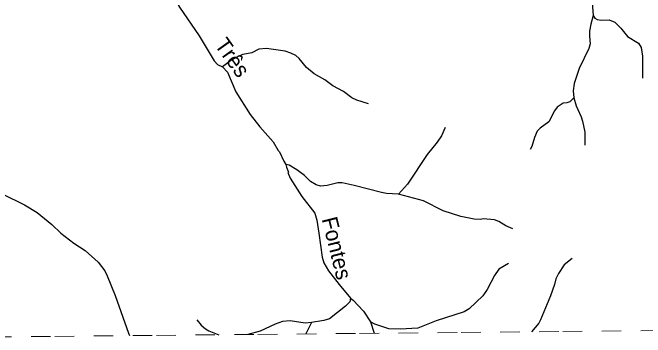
# Model space of a CAD drawing. Extents: x 346.5 to 372.4, y 7400.3 to 7428.2.
# Drawn here: x 358.605 to 361.849, y 7400.435 to 7402.098 of the extents above; entities that cross this region are included whole.
import ezdxf
from ezdxf.enums import TextEntityAlignment as Align

# ---------------------------------------------------------------- set-up
doc = ezdxf.new("R2010")
doc.units = 0
doc.header["$LTSCALE"] = 0.032
doc.linetypes.add('SHORT_DASHED', pattern=[2.7, 1.5, -1.2])
doc.layers.add('53', color=7, linetype='SHORT_DASHED', lineweight=13)
doc.layers.add('7', color=7, linetype='Continuous', lineweight=25)
doc.layers.add('61', color=7, linetype='Continuous')

msp = doc.modelspace()

# ---------------------------------------------------------------- linework, layer by layer
at = {"layer": '53'}
msp.add_lwpolyline([(358.2999, 7400.4352), (358.8209, 7400.4403), (359.3419, 7400.4453), (359.863, 7400.4502), (360.384, 7400.4552), (360.905, 7400.4602), (361.426, 7400.4651), (361.947, 7400.47), (362.4681, 7400.4749), (362.9891, 7400.4798), (363.5101, 7400.4846), (364.0311, 7400.4895), (364.5521, 7400.4943)], dxfattribs=at)
at = {"layer": '7'}
for p, q in [((360.1374, 7400.5116), (360.1088, 7400.4525)), ((360.4409, 7400.5141), (360.4592, 7400.4559))]:
    msp.add_line(p, q, dxfattribs=at)
for points in [[(361.3885, 7403.2094), (361.4008, 7403.1696), (361.4271, 7403.1274), (361.4319, 7403.1242), (361.4534, 7403.0293), (361.463, 7403.0038), (361.4981, 7402.9488), (361.6072, 7402.8189), (361.6288, 7402.7807), (361.6391, 7402.744), (361.6439, 7402.693), (361.6407, 7402.642), (361.6152, 7402.5496), (361.6136, 7402.5241), (361.6152, 7402.4603), (361.6327, 7402.3583), (361.6327, 7402.3041), (361.6232, 7402.2587), (361.5913, 7402.2165), (361.5754, 7402.175), (361.5819, 7402.0837)], [(359.2743, 7402.5266), (359.3296, 7402.4269), (359.3941, 7402.2547), (359.4132, 7402.2117), (359.4372, 7402.1686), (359.4611, 7402.1256), (359.5623, 7401.979), (359.6388, 7401.8507), (359.6555, 7401.833), (359.6805, 7401.821)], [(361.5819, 7402.0837), (361.5706, 7402.0387), (361.5634, 7402.0029), (361.5626, 7401.9774), (361.5658, 7401.9391), (361.5594, 7401.9136), (361.51, 7401.8116), (361.4845, 7401.7351), (361.4797, 7401.6969), (361.4822, 7401.6611)], [(361.5819, 7402.0837), (361.5904, 7402.0702), (361.6025, 7402.0626), (361.6248, 7402.0602), (361.6638, 7402.0618), (361.6933, 7402.0499), (361.7244, 7402.0188), (361.7571, 7401.9758), (361.8144, 7401.9415), (361.8272, 7401.92), (361.8352, 7401.8754), (361.8352, 7401.763)], [(360.4302, 7401.6315), (360.3704, 7401.649), (360.3441, 7401.6626), (360.3011, 7401.6945), (360.2477, 7401.7231), (360.2054, 7401.7534), (360.1504, 7401.7853), (360.1122, 7401.8172), (360.0739, 7401.8626), (360.0564, 7401.8785), (360.0309, 7401.8913), (360.0022, 7401.9001), (359.9066, 7401.9136), (359.8667, 7401.9104), (359.8309, 7401.8921), (359.7854, 7401.8833), (359.7679, 7401.8761), (359.7287, 7401.8561), (359.6805, 7401.821)], [(359.6805, 7401.821), (359.7073, 7401.7933), (359.7496, 7401.6921), (359.8229, 7401.5757), (359.8723, 7401.5128), (359.9416, 7401.437), (359.9671, 7401.3916), (359.9735, 7401.3852), (359.9949, 7401.3372), (360.0065, 7401.32)], [(361.4822, 7401.6611), (361.4622, 7401.6418), (361.4471, 7401.6355), (361.4279, 7401.6339), (361.3969, 7401.614), (361.3833, 7401.5948), (361.3538, 7401.5391), (361.3092, 7401.5056), (361.2941, 7401.4904), (361.2805, 7401.4578), (361.2677, 7401.4131), (361.2582, 7401.3964)], [(361.4822, 7401.6611), (361.4941, 7401.6203), (361.5204, 7401.5646), (361.5275, 7401.5422), (361.5387, 7401.4865), (361.5387, 7401.4187)], [(360.8223, 7401.5096), (360.8039, 7401.4673), (360.7824, 7401.4355), (360.7306, 7401.3717), (360.6294, 7401.2203), (360.5843, 7401.1691)], [(360.0065, 7401.32), (360.0086, 7401.3062), (360.0193, 7401.2812), (360.0165, 7401.2785), (360.0277, 7401.2506), (360.0883, 7401.1565), (360.1552, 7401.0704), (360.1656, 7401.0354), (360.1743, 7400.9684), (360.1919, 7400.8457), (360.2006, 7400.817), (360.2253, 7400.7756), (360.2795, 7400.7054), (360.338, 7400.6363)], [(360.5843, 7401.1691), (360.5218, 7401.1716), (360.4963, 7401.1764), (360.3561, 7401.2131), (360.2955, 7401.2258), (360.2732, 7401.2258), (360.2174, 7401.2123), (360.1839, 7401.2099), (360.1616, 7401.2163), (360.1329, 7401.2338), (360.1018, 7401.2641), (360.0628, 7401.2936), (360.0222, 7401.3169), (360.0065, 7401.32)], [(358.5518, 7401.1708), (358.6665, 7401.1135), (358.7303, 7401.0752), (358.8068, 7401.0131), (358.8514, 7400.9692), (358.9184, 7400.9166), (358.9773, 7400.88), (359.0435, 7400.8194), (359.0777, 7400.7756), (359.0905, 7400.7501), (359.1303, 7400.6497), (359.1997, 7400.4568), (359.2037, 7400.444)], [(361.1697, 7400.99), (361.1339, 7401.0067), (361.0988, 7401.0282), (361.0765, 7401.0362), (361.0175, 7401.0417), (361.0048, 7401.0386), (360.9713, 7401.0402), (360.9028, 7401.0537), (360.8135, 7401.0832), (360.7115, 7401.1342), (360.5843, 7401.1691)], [(361.4742, 7400.8385), (361.4335, 7400.8059), (361.4048, 7400.7628), (361.3897, 7400.7341), (361.3841, 7400.7054), (361.3634, 7400.6481), (361.3116, 7400.5245), (361.3028, 7400.507), (361.2664, 7400.4636)], [(361.1474, 7400.8138), (361.0988, 7400.7843), (361.0757, 7400.7517), (361.0382, 7400.6799), (361.0159, 7400.648), (360.9458, 7400.5811), (360.9203, 7400.5652), (360.7768, 7400.5197), (360.6828, 7400.4815), (360.5919, 7400.4775), (360.5346, 7400.4791), (360.462, 7400.5024), (360.4409, 7400.5141)], [(360.338, 7400.6363), (360.3349, 7400.6174), (360.3122, 7400.5947), (360.2293, 7400.5301), (360.2014, 7400.5213), (360.1374, 7400.5116)], [(360.338, 7400.6363), (360.3518, 7400.6253), (360.4039, 7400.5684), (360.4409, 7400.5141)], [(359.5487, 7400.5253), (359.5719, 7400.4974), (359.5942, 7400.4791), (359.6109, 7400.4688), (359.663, 7400.4483)], [(360.1374, 7400.5116), (360.1058, 7400.5081), (360.0277, 7400.519), (359.9895, 7400.5166), (359.9512, 7400.503), (359.8747, 7400.4663), (359.8117, 7400.4497)]]:
    msp.add_lwpolyline(points, dxfattribs=at)

# ---------------------------------------------------------------- texts
at = {"layer": '61'}
for s, rotation, p in [('Três', 305.431, (359.6996, 7401.8454)), ('Fontes', 284.036, (360.2288, 7400.8826))]:
    msp.add_text(s, height=0.08, rotation=rotation, dxfattribs=at).set_placement(p, align=Align.CENTER)

doc.saveas('drawing.dxf')
